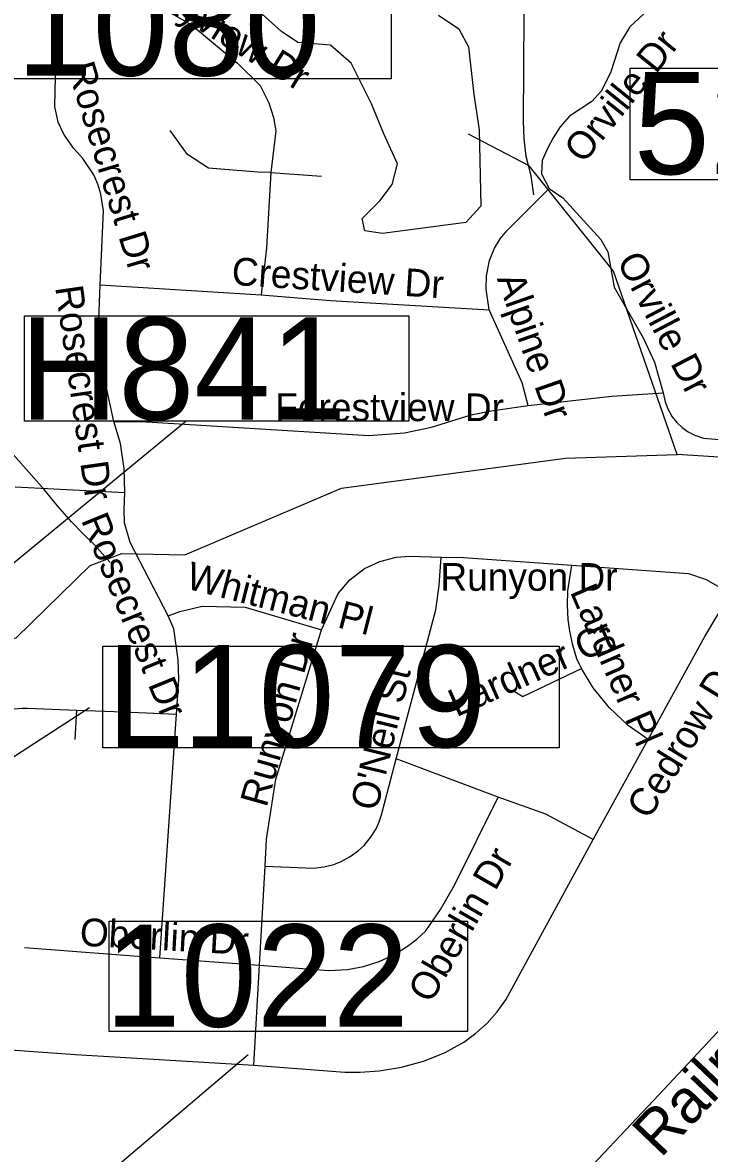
# Model space of a CAD drawing. Extents: x 1662474 to 1856135, y 779280 to 917889.
# Drawn here: x 1714192 to 1716545, y 810641 to 814512 of the extents above; entities that cross this region are included whole.
import ezdxf

# ---------------------------------------------------------------- set-up
doc = ezdxf.new("R2010")
doc.units = 0
for name, color, linetype in [('Exist Hydrographic Misc Water Feature', 7, 'Continuous'), ('Exist Hydrographic Pond Under 1500 Sq Ft', 7, 'Continuous'), ('Exist Railroad Mainline', 7, 'Continuous'), ('Exist Railroad Mainline Label', 7, 'Continuous'), ('Exist Road Non-System Structure Non-Sys NCDOT Number Label', 7, 'Continuous'), ('Exist Road Non-System Type 51', 7, 'Continuous'), ('Exist Road Non-System Type 51 Label', 7, 'Continuous'), ('Exist Road Primary Interstate Structure Cantilever Sign Number Label', 7, 'Continuous'), ('Exist Road Primary US Structure Ovrhead Sign CELL', 7, 'Continuous'), ('Exist Road Secondary Structure Standard Bridge Number Label', 7, 'Continuous'), ('Scratch_Level_2', 7, 'Continuous')]:
    doc.layers.add(name, color=color, linetype=linetype)

msp = doc.modelspace()

# ---------------------------------------------------------------- linework, layer by layer
at = {"layer": 'Exist Hydrographic Misc Water Feature'}
for points in [[(1715944.3, 813922.4), (1715934.9, 813988.4), (1715917.6, 814054.6), (1715910.2, 814114.7), (1715908.6, 814174.7), (1715910.2, 814540.8), (1715913.1, 814638.9), (1715923.7, 814706.7), (1715940.4, 814778.6), (1715952.9, 814834.5), (1715972.3, 814974.4), (1715978.1, 815162.4), (1715976.5, 815218.4), (1715975.1, 815272.4), (1715973.5, 815314.5)], [(1716435.3, 813033.3), (1716216.3, 813661.3), (1715928.3, 814021.7), (1715720.3, 814131)], [(1714491.8, 812663.6), (1714440.5, 812722.2), (1714400.8, 812760.6), (1714359.3, 812802.9), (1714311.8, 812857.5), (1714266.3, 812913.9), (1714105.8, 813093.4)], [(1711488.2, 810813.2), (1711597.2, 810912.7), (1711750.2, 811218.2), (1711794.2, 811394.5), (1712113.2, 811667), (1712391.2, 811947), (1712501.2, 812122), (1712677.2, 812220.2), (1713252.2, 812221.6), (1713403.2, 812294), (1713529.2, 812403.1), (1713637.3, 812443.5), (1714054.3, 812382.6), (1714170.2, 812406.5), (1714423.2, 812654), (1714532.2, 812694.5), (1714748.3, 812690), (1715284.3, 812918.8), (1716052.3, 813021.3), (1716435.3, 813033.3)], [(1717903.3, 812159.8), (1717862.3, 812301.8), (1717673.3, 812522.3), (1717449.3, 812664.7), (1717167.4, 812883.8), (1716902.3, 813004.1), (1716435.3, 813033.3)]]:
    msp.add_lwpolyline(points, dxfattribs=at)
at = {"layer": 'Exist Hydrographic Pond Under 1500 Sq Ft'}
for points in [[(1715757, 814145.2), (1715761.7, 813883.7), (1715710.3, 813827.6), (1715425.2, 813790.3), (1715364.5, 813799.6), (1715355.1, 813841.6), (1715415.9, 813902.3), (1715457.9, 813958.4), (1715476.6, 814028.5), (1715429.9, 814131.2), (1715387.8, 814234), (1715317.7, 814374.1), (1715247.6, 814434.8), (1715135.5, 814444.2), (1715079.4, 814481.5), (1714925.2, 814621.6)], [(1715616.8, 814537.6), (1715686.9, 814490.9), (1715719.6, 814430.1), (1715738.3, 814266.7), (1715757, 814145.2)]]:
    msp.add_lwpolyline(points, dxfattribs=at)
at = {"layer": 'Exist Railroad Mainline'}
msp.add_lwpolyline([(1713606.6, 808389.1), (1713712.6, 808419.7), (1713753.6, 808435.7), (1713824.5, 808464.4), (1713892.3, 808490.9), (1713965.3, 808528.2), (1714005.5, 808538.5), (1714111.1, 808596.5), (1714202.4, 808650.3), (1714259.1, 808691.8), (1714352.7, 808762.6), (1714455.9, 808850.9), (1714549.5, 808936.3), (1715012.4, 809420), (1715388, 809806), (1715730.1, 810166.9), (1716087.5, 810539.5), (1716372.3, 810841.3), (1716606, 811091.1)], dxfattribs=at)
at = {"layer": 'Exist Road Non-System Structure Non-Sys NCDOT Number Label'}
msp.add_line((1711805.1, 810722.8), (1714752.6, 813149.3), dxfattribs=at)
msp.add_lwpolyline([(1714198.2, 813508.5), (1715515.3, 813508.5), (1715515.3, 813147.3), (1714198.2, 813147.3)], close=True, dxfattribs=at)
at = {"layer": 'Exist Road Non-System Type 51'}
for p, q in [((1715042.8, 813999.4), (1715216.8, 813986.9)), ((1714457.6, 813614.1), (1715009.4, 813580)), ((1714166.9, 812923.4), (1714542.5, 812903.9)), ((1714372.1, 812058), (1714378.4, 812158.2)), ((1714661.9, 811310), (1714719.6, 812144.4)), ((1716147.1, 811714.9), (1716335.6, 812057.8)), ((1715822, 811860.1), (1715472.1, 811992.1)), ((1715003.6, 811285), (1715023, 811623.6)), ((1714198.4, 811345.4), (1714661.9, 811310)), ((1714661.9, 811310), (1715003.6, 811285)), ((1714984.4, 810942.5), (1715003.6, 811285))]:
    msp.add_line(p, q, dxfattribs=at)
for points in [[(1716606.5, 814808.9), (1716272.4, 814498.1), (1716240.1, 814443.2), (1716208.1, 814343.5), (1716175.8, 814278.9), (1716141.9, 814241.9), (1716066.1, 814192.1), (1716034.1, 814155.4), (1716009.6, 814118.1), (1715990.2, 814081), (1715972.6, 814040.6), (1715969.5, 813995.2), (1715996.2, 813944)], [(1714457.6, 813614.1), (1714469.2, 813868.2), (1714459.9, 813925.4), (1714449.6, 813958.8), (1714436.1, 813990.8), (1714399.1, 814046.9), (1714367.1, 814082.6), (1714333, 814130.7), (1714314.1, 814171.6), (1714302.1, 814225.4), (1714311, 814577.9)], [(1714311, 814577.9), (1714624.6, 814566.9), (1714704.4, 814542.8), (1714770.9, 814505.2), (1714928, 814373.7), (1715006.2, 814297.4), (1715035.4, 814237.8), (1715051.9, 814187.6), (1715059.5, 814141.9), (1715042.8, 813999.4)], [(1715042.8, 813999.4), (1714998.4, 814000.2), (1714828.6, 814013.9), (1714757.6, 814060.9), (1714697.4, 814143.5)], [(1715042.8, 813999.4), (1715028, 813741.7), (1715009.4, 813580)], [(1715790.5, 813529.6), (1715781, 813599.7), (1715781.2, 813645.1), (1715791.8, 813698.4), (1715809.1, 813740.7), (1715828, 813772.1), (1715850.9, 813799.9), (1715996.2, 813944)], [(1715996.2, 813944), (1716043.2, 813912), (1716172.9, 813769.8), (1716196.8, 813728), (1716219.4, 813606.5), (1716318.9, 813433.6), (1716356.9, 813350.4), (1716387.4, 813244.9)], [(1714504.6, 813147.2), (1714481.6, 813251.7), (1714459.5, 813378.4), (1714453.5, 813493.7), (1714457.6, 813614.1)], [(1715009.4, 813580), (1715247.1, 813560.6), (1715790.5, 813529.6)], [(1715924.4, 813201.2), (1715903.6, 813278.7), (1715790.5, 813529.6)], [(1715924.4, 813201.2), (1716211.1, 813233.6), (1716387.4, 813244.9)], [(1716387.4, 813244.9), (1716393.9, 813213.9), (1716402.5, 813190.5), (1716418, 813163.2), (1716434, 813143.8), (1716452.1, 813125.9), (1716472.9, 813111.5), (1716495.1, 813100.2), (1716525.1, 813090), (1716690.5, 813075.6), (1716762.1, 813081.9), (1716845.9, 813133)], [(1714504.6, 813147.2), (1714598.9, 813146.9), (1715378.9, 813099.2), (1715500.8, 813107.9), (1715592.9, 813127.5), (1715729.6, 813169), (1715798.1, 813183.7), (1715924.4, 813201.2)], [(1714542.5, 812903.9), (1714539.6, 812984.8), (1714527.8, 813070.9), (1714504.6, 813147.2)], [(1714691.2, 812481.6), (1714560.4, 812732.5), (1714540.9, 812799.7), (1714539.6, 812846.4), (1714542.5, 812903.9)], [(1715216.5, 812433.4), (1715273.1, 812557.2), (1715313.9, 812604.7), (1715364, 812643), (1715415.9, 812667.4), (1715471.6, 812682.4), (1715518.6, 812685.9), (1715626.6, 812682.7)], [(1715472.1, 811992.1), (1715608.1, 812502.4), (1715619.4, 812584.8), (1715626.6, 812682.7)], [(1715626.6, 812682.7), (1715702.9, 812680.9), (1716073.6, 812654.6)], [(1716106.5, 812301.2), (1716091.5, 812333.9), (1716077.1, 812380.6), (1716066.6, 812429.1), (1716061.4, 812468.2), (1716058.8, 812517.6), (1716060.2, 812566.9), (1716073.6, 812654.6)], [(1716073.6, 812654.6), (1716473.4, 812626.5), (1716534.6, 812606), (1716617.5, 812558.2)], [(1716335.6, 812057.8), (1716530.1, 812411), (1716617.5, 812558.2)], [(1714691.2, 812481.6), (1714730.4, 812496.6), (1714807.4, 812514.4), (1714954.9, 812510.8), (1715216.5, 812433.4)], [(1714719.6, 812144.4), (1714728, 812264.2), (1714724.9, 812330.2), (1714710.6, 812437), (1714691.2, 812481.6)], [(1715023, 811623.6), (1715028, 811716.8), (1715060.1, 811921.5), (1715216.5, 812433.4)], [(1715870.5, 812227.2), (1715906.5, 812205.2), (1716106.5, 812301.2)], [(1716335.6, 812057.8), (1716267.4, 812106.2), (1716202.6, 812166.7), (1716147.1, 812235.2), (1716106.5, 812301.2)], [(1713966.6, 812060.6), (1713989.8, 812085), (1714009.4, 812102.9), (1714025.1, 812115.8), (1714042.2, 812127.9), (1714057.6, 812136.5), (1714075.6, 812143.6), (1714093.9, 812149.6), (1714106.5, 812153), (1714124.9, 812157.2), (1714144.4, 812160.9), (1714163.5, 812163.2), (1714189.1, 812164.9), (1714208.4, 812164.6), (1714378.4, 812158.2)], [(1714378.4, 812158.2), (1714538.2, 812152.5), (1714719.6, 812144.4)], [(1715023, 811623.6), (1715189.4, 811617.6), (1715224.4, 811621.8), (1715258.5, 811630.4), (1715283.4, 811640.2), (1715314.4, 811656.9), (1715342.8, 811677.4), (1715361.9, 811695.2), (1715384.4, 811722.6), (1715403.1, 811752.2), (1715414.1, 811776.1), (1715422.2, 811799.8), (1715472.1, 811992.1)], [(1715003.6, 811285), (1715241.9, 811267.2), (1715305.4, 811270.6), (1715360.4, 811280.9), (1715413.4, 811297.4), (1715463.8, 811321), (1715511.2, 811350.1), (1715542.8, 811374), (1715573.6, 811402.9), (1715623.6, 811476.1), (1715672.1, 811559.6), (1715822, 811860.1)], [(1716147.1, 811714.9), (1715985, 811802.1), (1715822, 811860.1)], [(1714984.4, 810942.5), (1715296.5, 810918.7), (1715348.5, 810918.4), (1715413.4, 810923.1), (1715490.2, 810935.7), (1715565.6, 810956.7), (1715638.2, 810985.4), (1715703.6, 811021), (1715745.4, 811052), (1715783.4, 811086.6), (1715818, 811124.9), (1715847.9, 811166.9), (1716147.1, 811714.9)], [(1712839.9, 811042.8), (1712930.9, 811059.4), (1713015.1, 811066.7), (1713095.8, 811066.4), (1713225.6, 811061.2), (1714373.1, 810979.5), (1714984.4, 810942.5)]]:
    msp.add_lwpolyline(points, dxfattribs=at)
at = {"layer": 'Exist Road Primary Interstate Structure Cantilever Sign Number Label'}
msp.add_line((1711770.3, 810452.3), (1714421.8, 812167.8), dxfattribs=at)
msp.add_lwpolyline([(1714467.6, 812377.9), (1716030.5, 812377.9), (1716030.5, 812029), (1714467.6, 812029)], close=True, dxfattribs=at)
at = {"layer": 'Exist Road Primary US Structure Ovrhead Sign CELL'}
msp.add_lwpolyline([(1713875.3, 814693.6), (1715455.3, 814693.6), (1715455.3, 814319.5), (1713875.3, 814319.5)], close=True, dxfattribs=at)
at = {"layer": 'Exist Road Secondary Structure Standard Bridge Number Label'}
msp.add_lwpolyline([(1716273.6, 814356.2), (1716917.8, 814356.2), (1716917.8, 813973.9), (1716273.6, 813973.9)], close=True, dxfattribs=at)
at = {"layer": 'Scratch_Level_2'}
msp.add_line((1711657.6, 808174.7), (1714964.8, 810979.1), dxfattribs=at)
msp.add_lwpolyline([(1714488.4, 811435.8), (1715716.1, 811435.8), (1715716.1, 811057.7), (1714488.4, 811057.7)], close=True, dxfattribs=at)

# ---------------------------------------------------------------- texts
at = {"layer": 'Exist Railroad Mainline Label'}
msp.add_text('Railroad', height=150, rotation=46.4229, dxfattribs=at).set_placement((1716377.7, 810622.1))
at = {"layer": 'Exist Road Non-System Structure Non-Sys NCDOT Number Label'}
msp.add_text('H841', height=350, dxfattribs=at).set_placement((1714182.2, 813153.4))
at = {"layer": 'Exist Road Non-System Type 51 Label'}
for s, rotation, p in [('Loftyview Dr', 328.2686, (1714543.7, 814642.3)), ('Orville Dr', 51.1818, (1716114, 814026)), ('Rosecrest Dr', 286.8927, (1714343.5, 814361.7)), ('Crestview Dr', 356.3424, (1714906.5, 813614.7)), ('Orville Dr', 297.6651, (1716226.2, 813696.5)), ('Alpine Dr', 289.2819, (1715816.2, 813636.5)), ('Rosecrest Dr', 278.1255, (1714303.7, 813606.6)), ('Rosecrest Dr', 292.1695, (1714391.4, 812809.5)), ('Whitman Pl', 345.6031, (1714747.7, 812575.8)), ('Lardner Pl', 293.4159, (1716066.3, 812564.3)), ('Lardner Ct', 23.9747, (1715678.3, 812133.5)), ('Runyon Dr', 74.3484, (1715027.7, 811822.4)), ('Cedrow Dr', 58.4667, (1716337.9, 811779.9)), ("O'Neil St", 76.4566, (1715406.4, 811809.7)), ('Oberlin Dr', 60.1668, (1715590.4, 811150.4)), ('Oberlin Dr', 356.8051, (1714386.4, 811352.2))]:
    msp.add_text(s, height=95, rotation=rotation, dxfattribs=at).set_placement(p)
for s, p in [('Forestview Dr', (1715057.9, 813147.9)), ('Runyon Dr', (1715623.5, 812567))]:
    msp.add_text(s, height=95, dxfattribs=at).set_placement(p)
at = {"layer": 'Exist Road Primary Interstate Structure Cantilever Sign Number Label'}
msp.add_text('L1079', height=350, dxfattribs=at).set_placement((1714480.1, 812031))
at = {"layer": 'Exist Road Primary US Structure Ovrhead Sign CELL'}
msp.add_text('S1080', height=350, dxfattribs=at).set_placement((1713859.3, 814331.1))
at = {"layer": 'Exist Road Secondary Structure Standard Bridge Number Label'}
msp.add_text('52', height=350, dxfattribs=at).set_placement((1716286.2, 813993.7))
at = {"layer": 'Scratch_Level_2'}
msp.add_text('1022', height=350, dxfattribs=at).set_placement((1714473.9, 811074.3))

doc.saveas('drawing.dxf')
